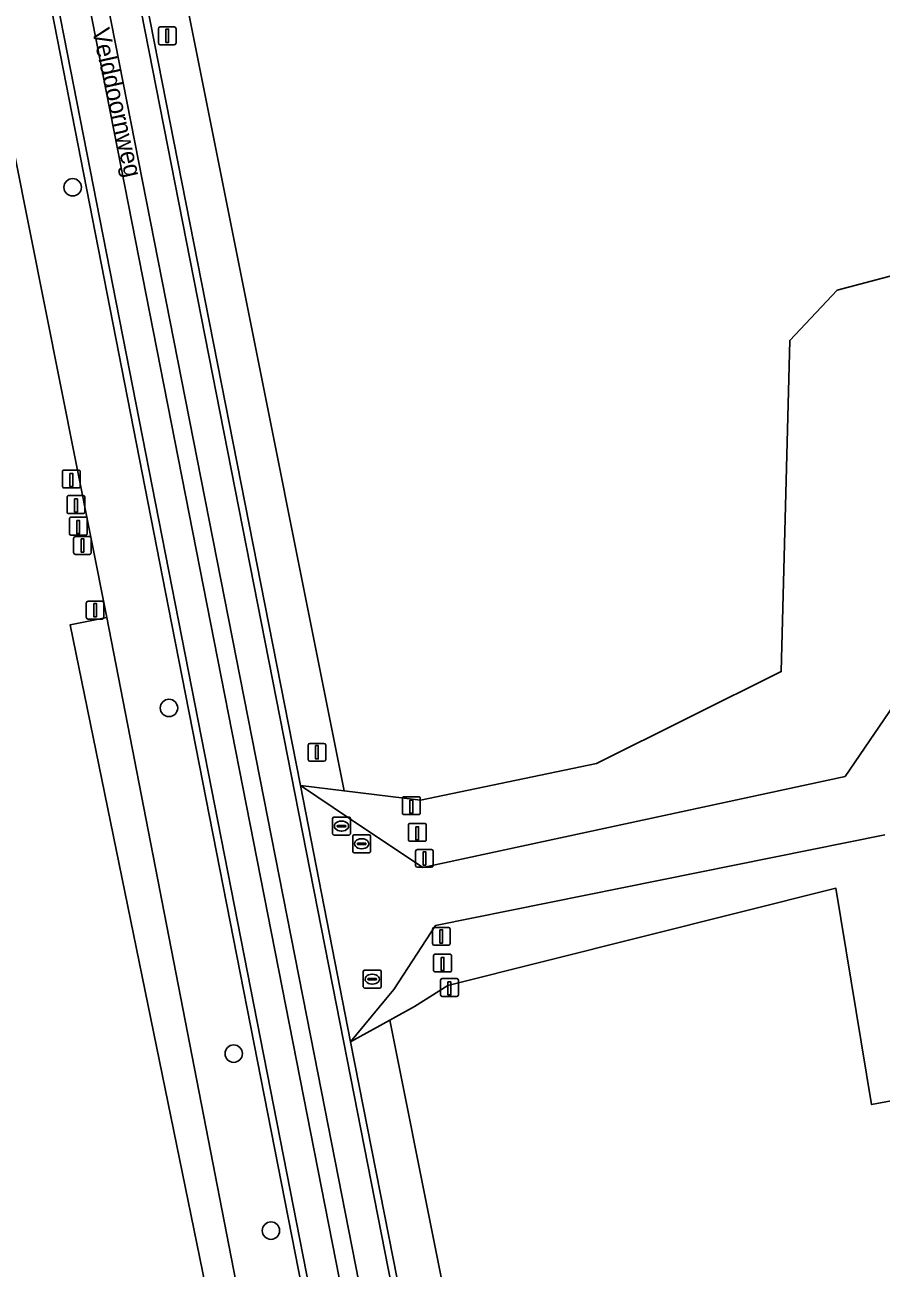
# Model space of a CAD drawing. Extents: x 160203 to 161530, y 379528 to 381797.
# Drawn here: x 160875 to 160923.2, y 380067.5 to 380137.4 of the extents above; entities that cross this region are included whole.
import ezdxf

# ---------------------------------------------------------------- set-up
doc = ezdxf.new("R2010")
doc.units = 0
for name, color, linetype in [('IMGEO_Afsluitpaal', 7, 'Continuous'), ('IMGEO_Berm_groen', 7, 'Continuous'), ('IMGEO_Berm_open', 7, 'Continuous'), ('IMGEO_Boom', 7, 'Continuous'), ('IMGEO_Brandkraan', 7, 'Continuous'), ('IMGEO_Groenvoorziening', 7, 'Continuous'), ('IMGEO_Lichtmast', 7, 'Continuous'), ('IMGEO_Loofbos', 7, 'Continuous'), ('IMGEO_Openbare_ruimte_label', 7, 'Continuous'), ('IMGEO_Paal', 7, 'Continuous'), ('IMGEO_Rijbaan_lokaal_gesloten', 7, 'Continuous'), ('IMGEO_Rijbaan_lokaal_halfverhard', 7, 'Continuous'), ('IMGEO_Rijbaan_lokaal_open', 7, 'Continuous'), ('IMGEO_Waterloop', 7, 'Continuous')]:
    doc.layers.add(name, color=color, linetype=linetype)

msp = doc.modelspace()

# ---------------------------------------------------------------- linework, layer by layer
at = {"layer": 'IMGEO_Afsluitpaal'}
for p, q in [((160877.74, 380107.756), (160877.74, 380108.556)), ((160877.74, 380108.556), (160877.74, 380107.756)), ((160877.84, 380108.656), (160878.63, 380108.656)), ((160878.63, 380108.656), (160877.84, 380108.656)), ((160878.73, 380108.556), (160878.73, 380107.756)), ((160878.73, 380107.756), (160878.73, 380108.556)), ((160878.63, 380107.656), (160877.84, 380107.656)), ((160877.84, 380107.656), (160878.63, 380107.656)), ((160878.449, 380104.117), (160878.449, 380104.917)), ((160878.449, 380104.917), (160878.449, 380104.117)), ((160878.549, 380105.017), (160879.339, 380105.017)), ((160879.339, 380105.017), (160878.549, 380105.017)), ((160879.439, 380104.917), (160879.439, 380104.117)), ((160879.439, 380104.117), (160879.439, 380104.917)), ((160879.339, 380104.017), (160878.549, 380104.017)), ((160878.549, 380104.017), (160879.339, 380104.017)), ((160896.986, 380090.153), (160896.986, 380090.953)), ((160896.986, 380090.953), (160896.986, 380090.153)), ((160897.086, 380091.053), (160897.876, 380091.053)), ((160897.876, 380091.053), (160897.086, 380091.053)), ((160897.976, 380090.953), (160897.976, 380090.153)), ((160897.976, 380090.153), (160897.976, 380090.953)), ((160897.876, 380090.053), (160897.086, 380090.053)), ((160897.086, 380090.053), (160897.876, 380090.053)), ((160897.937, 380085.769), (160897.937, 380086.569)), ((160897.937, 380086.569), (160897.937, 380085.769)), ((160898.037, 380086.669), (160898.827, 380086.669)), ((160898.827, 380086.669), (160898.037, 380086.669)), ((160898.927, 380086.569), (160898.927, 380085.769)), ((160898.927, 380085.769), (160898.927, 380086.569)), ((160898.827, 380085.669), (160898.037, 380085.669)), ((160898.037, 380085.669), (160898.827, 380085.669))]:
    msp.add_line(p, q, dxfattribs=at)
for points in [[(160878.16, 380108.531), (160878.31, 380108.531), (160878.31, 380107.781), (160878.16, 380107.781), (160878.16, 380108.531)], [(160878.869, 380104.892), (160879.019, 380104.892), (160879.019, 380104.142), (160878.869, 380104.142), (160878.869, 380104.892)], [(160897.406, 380090.928), (160897.556, 380090.928), (160897.556, 380090.178), (160897.406, 380090.178), (160897.406, 380090.928)], [(160898.357, 380086.544), (160898.507, 380086.544), (160898.507, 380085.794), (160898.357, 380085.794), (160898.357, 380086.544)]]:
    msp.add_lwpolyline(points, dxfattribs=at)
for centre, start, end in [((160877.84, 380108.556), 90, 180), ((160877.84, 380108.556), 90, 180), ((160878.63, 380108.556), 0, 90), ((160878.63, 380108.556), 360, 90), ((160877.84, 380107.756), 180, 270), ((160877.84, 380107.756), 180, 270), ((160878.63, 380107.756), 270, 0), ((160878.63, 380107.756), 270, 0), ((160878.549, 380104.917), 90, 180), ((160878.549, 380104.917), 90, 180), ((160879.339, 380104.917), 0, 90), ((160879.339, 380104.917), 360, 90), ((160878.549, 380104.117), 180, 270), ((160878.549, 380104.117), 180, 270), ((160879.339, 380104.117), 270, 0), ((160879.339, 380104.117), 270, 0), ((160897.086, 380090.953), 90, 180), ((160897.086, 380090.953), 90, 180), ((160897.876, 380090.953), 0, 90), ((160897.876, 380090.953), 360, 90), ((160897.086, 380090.153), 180, 270), ((160897.086, 380090.153), 180, 270), ((160897.876, 380090.153), 270, 0), ((160897.876, 380090.153), 270, 0), ((160898.037, 380086.569), 90, 180), ((160898.037, 380086.569), 90, 180), ((160898.827, 380086.569), 0, 90), ((160898.827, 380086.569), 360, 90), ((160898.037, 380085.769), 180, 270), ((160898.037, 380085.769), 180, 270), ((160898.827, 380085.769), 270, 0), ((160898.827, 380085.769), 270, 0)]:
    msp.add_arc(centre, 0.1, start, end, dxfattribs=at)
at = {"layer": 'IMGEO_Berm_groen'}
msp.add_lwpolyline([(160895.533, 380081.45), (160893.315, 380080.226), (160905.256, 380019.672), (160908.269, 380017.71)], close=True, dxfattribs=at)
at = {"layer": 'IMGEO_Berm_open'}
msp.add_lwpolyline([(160867.75, 380199.041), (160861.56, 380230.469), (160858.975, 380243.591), (160857.899, 380243.338), (160860.551, 380229.96), (160866.722, 380198.834), (160874.382, 380160.192), (160915.855, 379949.015), (160917.449, 379940.569), (160918.479, 379940.789), (160916.864, 379949.182), (160891.303, 380079.455)], close=True, dxfattribs=at)
at = {"layer": 'IMGEO_Boom'}
for centre in [(160877.685, 380128.302), (160883.106, 380099.015), (160886.747, 380079.57), (160888.845, 380069.614)]:
    msp.add_circle(centre, 0.489, dxfattribs=at)
at = {"layer": 'IMGEO_Brandkraan'}
for p, q in [((160892.388, 380092.869), (160893.24, 380092.869)), ((160892.313, 380091.943), (160892.313, 380092.795)), ((160892.572, 380092.363), (160892.572, 380092.375)), ((160893.01, 380092.326), (160892.612, 380092.326)), ((160892.615, 380092.412), (160893.013, 380092.412)), ((160892.801, 380092.649), (160892.826, 380092.649)), ((160893.056, 380092.375), (160893.056, 380092.363)), ((160893.314, 380092.795), (160893.314, 380091.943)), ((160893.24, 380091.869), (160892.388, 380091.869)), ((160892.824, 380092.089), (160892.799, 380092.089)), ((160893.448, 380090.949), (160893.448, 380091.801)), ((160893.523, 380091.875), (160894.375, 380091.875)), ((160893.75, 380091.418), (160894.148, 380091.418)), ((160893.936, 380091.655), (160893.961, 380091.655)), ((160894.449, 380091.801), (160894.449, 380090.949)), ((160894.375, 380090.875), (160893.523, 380090.875)), ((160893.707, 380091.369), (160893.707, 380091.381)), ((160894.145, 380091.332), (160893.747, 380091.332)), ((160893.959, 380091.095), (160893.934, 380091.095)), ((160894.191, 380091.381), (160894.191, 380091.369)), ((160894.042, 380083.334), (160894.042, 380084.186)), ((160894.117, 380084.26), (160894.969, 380084.26)), ((160894.301, 380083.754), (160894.301, 380083.766)), ((160894.739, 380083.717), (160894.341, 380083.717)), ((160894.344, 380083.803), (160894.742, 380083.803)), ((160894.53, 380084.04), (160894.555, 380084.04)), ((160894.785, 380083.766), (160894.785, 380083.754)), ((160895.043, 380084.186), (160895.043, 380083.334)), ((160894.969, 380083.26), (160894.117, 380083.26)), ((160894.553, 380083.48), (160894.528, 380083.48))]:
    msp.add_line(p, q, dxfattribs=at)
for points in [[(160892.388, 380092.869), (160893.24, 380092.869)], [(160892.313, 380091.943), (160892.313, 380092.795)], [(160893.314, 380092.795), (160893.314, 380091.943)], [(160893.24, 380091.869), (160892.388, 380091.869)], [(160893.448, 380090.949), (160893.448, 380091.801)], [(160893.523, 380091.875), (160894.375, 380091.875)], [(160894.449, 380091.801), (160894.449, 380090.949)], [(160894.375, 380090.875), (160893.523, 380090.875)], [(160894.042, 380083.334), (160894.042, 380084.186)], [(160894.117, 380084.26), (160894.969, 380084.26)], [(160895.043, 380084.186), (160895.043, 380083.334)], [(160894.969, 380083.26), (160894.117, 380083.26)]]:
    msp.add_lwpolyline(points, dxfattribs=at)
for centre, radius, start, end in [((160892.39, 380092.793), 0.0765, 91.55205, 178.44795), ((160892.39, 380092.793), 0.0765, 91.55205, 178.44795), ((160893.238, 380092.793), 0.0765, 1.55205, 88.44795), ((160893.238, 380092.793), 0.0765, 1.55205, 88.44795), ((160892.612, 380092.372), 0.0403, 85.87752, 175.75265), ((160892.609, 380092.362), 0.0366, 178.93798, 274.71019), ((160893.013, 380092.369), 0.043, 264.86636, 352.45326), ((160893.017, 380092.374), 0.0386, 1.73085, 96.63898), ((160892.39, 380091.945), 0.0765, 181.55205, 268.44795), ((160892.39, 380091.945), 0.0765, 181.55205, 268.44795), ((160893.238, 380091.945), 0.0765, 271.55205, 358.44795), ((160893.238, 380091.945), 0.0765, 271.55205, 358.44795), ((160893.525, 380091.799), 0.0765, 91.55205, 178.44795), ((160893.525, 380091.799), 0.0765, 91.55205, 178.44795), ((160893.747, 380091.378), 0.0403, 85.87752, 175.75265), ((160894.152, 380091.38), 0.0386, 1.73085, 96.63898), ((160894.373, 380091.799), 0.0765, 1.55205, 88.44795), ((160894.373, 380091.799), 0.0765, 1.55205, 88.44795), ((160893.525, 380090.951), 0.0765, 181.55205, 268.44795), ((160893.525, 380090.951), 0.0765, 181.55205, 268.44795), ((160893.744, 380091.368), 0.0366, 178.93798, 274.71019), ((160894.148, 380091.375), 0.043, 264.86636, 352.45326), ((160894.373, 380090.951), 0.0765, 271.55205, 358.44795), ((160894.373, 380090.951), 0.0765, 271.55205, 358.44795), ((160894.119, 380084.184), 0.0765, 91.55205, 178.44795), ((160894.119, 380084.184), 0.0765, 91.55205, 178.44795), ((160894.341, 380083.763), 0.0403, 85.87752, 175.75265), ((160894.338, 380083.753), 0.0366, 178.93798, 274.71019), ((160894.742, 380083.76), 0.043, 264.86636, 352.45326), ((160894.746, 380083.765), 0.0386, 1.73085, 96.63898), ((160894.967, 380084.184), 0.0765, 1.55205, 88.44795), ((160894.967, 380084.184), 0.0765, 1.55205, 88.44795), ((160894.119, 380083.336), 0.0765, 181.55205, 268.44795), ((160894.119, 380083.336), 0.0765, 181.55205, 268.44795), ((160894.967, 380083.336), 0.0765, 271.55205, 358.44795), ((160894.967, 380083.336), 0.0765, 271.55205, 358.44795)]:
    msp.add_arc(centre, radius, start, end, dxfattribs=at)
for centre, major_axis, ratio, start_param, end_param in [((160892.8, 380092.369), (-0.387, 0.002), 0.722429, 4.712389, 7.853982), ((160892.825, 380092.369), (-0.39, 0.002), 0.717154, 1.570796, 4.712389), ((160893.935, 380091.375), (-0.387, 0.002), 0.722429, 4.712389, 7.853982), ((160893.96, 380091.375), (-0.39, 0.002), 0.717154, 1.570796, 4.712389), ((160894.529, 380083.76), (-0.387, 0.002), 0.722429, 4.712389, 7.853982), ((160894.554, 380083.76), (-0.39, 0.002), 0.717154, 1.570796, 4.712389)]:
    msp.add_ellipse(centre, major_axis=major_axis, ratio=ratio, start_param=start_param, end_param=end_param, dxfattribs=at)
at = {"layer": 'IMGEO_Groenvoorziening'}
for points in [[(160858.585, 380228.968), (160856.352, 380240.258), (160852.661, 380239.334), (160879.617, 380104.11), (160888.682, 380057.421), (160900.057, 380000), (160907.97, 379960.368), (160913.18, 379936.681), (160911.655, 379936.379), (160912.186, 379932.168), (160913.952, 379932.527), (160916.604, 379919.613), (160923.442, 379886.324)], [(160926.044, 379887.123), (160925.694, 379888.565), (160919.399, 379920.083), (160913.703, 379948.599), (160883.085, 380104.658), (160872.358, 380159.336), (160864.629, 380198.41), (160858.585, 380228.968)], [(160939.157, 380115.876), (160930.535, 380117.947), (160928.697, 380120.046), (160927.725, 380124.364), (160920.712, 380122.517), (160918.035, 380119.689), (160917.557, 380101.063), (160907.156, 380095.894), (160897.258, 380093.833), (160892.955, 380094.353), (160890.502, 380094.649), (160893.265, 380092.8), (160897.383, 380090.043), (160921.152, 380095.162), (160925.838, 380101.995)], [(160923.39, 380091.872), (160898.101, 380086.776), (160895.76, 380083.184), (160895.298, 380082.625), (160893.315, 380080.226), (160895.533, 380081.45), (160896.929, 380082.22), (160898.801, 380083.398), (160920.634, 380088.87), (160922.642, 380076.701), (160947.339, 380081.313)]]:
    msp.add_lwpolyline(points, dxfattribs=at)
msp.add_lwpolyline([(160892.955, 380094.353), (160879.549, 380161.442), (160877.378, 380161.397), (160890.502, 380094.649)], close=True, dxfattribs=at)
at = {"layer": 'IMGEO_Lichtmast'}
for p, q in [((160882.514, 380136.424), (160882.514, 380137.224)), ((160882.514, 380137.224), (160882.514, 380136.424)), ((160882.614, 380137.324), (160883.404, 380137.324)), ((160883.404, 380137.324), (160882.614, 380137.324)), ((160883.504, 380137.224), (160883.504, 380136.424)), ((160883.504, 380136.424), (160883.504, 380137.224)), ((160883.404, 380136.324), (160882.614, 380136.324)), ((160882.614, 380136.324), (160883.404, 380136.324)), ((160891.039, 380097.02), (160891.829, 380097.02)), ((160891.829, 380097.02), (160891.039, 380097.02)), ((160890.939, 380096.12), (160890.939, 380096.92)), ((160890.939, 380096.92), (160890.939, 380096.12)), ((160891.929, 380096.92), (160891.929, 380096.12)), ((160891.929, 380096.12), (160891.929, 380096.92)), ((160891.829, 380096.02), (160891.039, 380096.02)), ((160891.039, 380096.02), (160891.829, 380096.02))]:
    msp.add_line(p, q, dxfattribs=at)
for points in [[(160882.934, 380137.199), (160883.084, 380137.199), (160883.084, 380136.449), (160882.934, 380136.449), (160882.934, 380137.199)], [(160891.359, 380096.895), (160891.509, 380096.895), (160891.509, 380096.145), (160891.359, 380096.145), (160891.359, 380096.895)]]:
    msp.add_lwpolyline(points, dxfattribs=at)
for centre, start, end in [((160882.614, 380137.224), 90, 180), ((160882.614, 380137.224), 90, 180), ((160883.404, 380137.224), 0, 90), ((160883.404, 380137.224), 360, 90), ((160882.614, 380136.424), 180, 270), ((160882.614, 380136.424), 180, 270), ((160883.404, 380136.424), 270, 0), ((160883.404, 380136.424), 270, 0), ((160891.039, 380096.92), 90, 180), ((160891.039, 380096.92), 90, 180), ((160891.829, 380096.92), 0, 90), ((160891.829, 380096.92), 360, 90), ((160891.039, 380096.12), 180, 270), ((160891.039, 380096.12), 180, 270), ((160891.829, 380096.12), 270, 0), ((160891.829, 380096.12), 270, 0)]:
    msp.add_arc(centre, 0.1, start, end, dxfattribs=at)
at = {"layer": 'IMGEO_Loofbos'}
for points in [[(160885.486, 380064.948), (160877.546, 380103.697), (160879.617, 380104.11), (160852.661, 380239.334)], [(160879.549, 380161.442), (160892.955, 380094.353), (160897.258, 380093.833), (160907.156, 380095.894), (160917.557, 380101.063), (160918.035, 380119.689), (160920.712, 380122.517), (160927.725, 380124.364), (160928.697, 380120.046), (160930.535, 380117.947), (160939.157, 380115.876), (160947.339, 380081.313), (160922.642, 380076.701), (160920.634, 380088.87), (160898.801, 380083.398), (160896.929, 380082.22), (160895.533, 380081.45), (160908.269, 380017.71)]]:
    msp.add_lwpolyline(points, dxfattribs=at)
at = {"layer": 'IMGEO_Paal'}
for p, q in [((160878.031, 380112.396), (160877.19, 380112.396)), ((160878.031, 380112.396), (160877.19, 380112.396)), ((160877.115, 380112.312), (160877.115, 380111.471)), ((160877.115, 380112.312), (160877.115, 380111.471)), ((160878.115, 380111.48), (160878.115, 380112.321)), ((160878.115, 380111.48), (160878.115, 380112.321)), ((160877.199, 380111.396), (160878.04, 380111.396)), ((160877.199, 380111.396), (160878.04, 380111.396)), ((160877.375, 380110.873), (160877.375, 380110.032)), ((160877.375, 380110.873), (160877.375, 380110.032)), ((160878.291, 380110.957), (160877.45, 380110.957)), ((160878.291, 380110.957), (160877.45, 380110.957)), ((160878.375, 380110.041), (160878.375, 380110.882)), ((160878.375, 380110.041), (160878.375, 380110.882)), ((160877.459, 380109.957), (160878.3, 380109.957)), ((160877.459, 380109.957), (160878.3, 380109.957)), ((160877.5, 380109.659), (160877.5, 380108.818)), ((160877.5, 380109.659), (160877.5, 380108.818)), ((160878.416, 380109.743), (160877.575, 380109.743)), ((160878.416, 380109.743), (160877.575, 380109.743)), ((160878.5, 380108.827), (160878.5, 380109.668)), ((160878.5, 380108.827), (160878.5, 380109.668)), ((160877.584, 380108.743), (160878.425, 380108.743)), ((160877.584, 380108.743), (160878.425, 380108.743)), ((160896.246, 380093.932), (160896.246, 380093.091)), ((160896.246, 380093.932), (160896.246, 380093.091)), ((160897.162, 380094.016), (160896.321, 380094.016)), ((160897.162, 380094.016), (160896.321, 380094.016)), ((160897.246, 380093.1), (160897.246, 380093.941)), ((160897.246, 380093.1), (160897.246, 380093.941)), ((160896.33, 380093.016), (160897.171, 380093.016)), ((160896.33, 380093.016), (160897.171, 380093.016)), ((160896.581, 380092.434), (160896.581, 380091.593)), ((160896.581, 380092.434), (160896.581, 380091.593)), ((160897.497, 380092.518), (160896.656, 380092.518)), ((160897.497, 380092.518), (160896.656, 380092.518)), ((160897.581, 380091.602), (160897.581, 380092.443)), ((160897.581, 380091.602), (160897.581, 380092.443)), ((160896.665, 380091.518), (160897.506, 380091.518)), ((160896.665, 380091.518), (160897.506, 380091.518)), ((160898.916, 380085.168), (160898.075, 380085.168)), ((160898.916, 380085.168), (160898.075, 380085.168)), ((160898, 380085.084), (160898, 380084.243)), ((160898, 380085.084), (160898, 380084.243)), ((160899, 380084.252), (160899, 380085.093)), ((160899, 380084.252), (160899, 380085.093)), ((160898.084, 380084.168), (160898.925, 380084.168)), ((160898.084, 380084.168), (160898.925, 380084.168)), ((160898.392, 380083.708), (160898.392, 380082.867)), ((160898.392, 380083.708), (160898.392, 380082.867)), ((160899.308, 380083.792), (160898.467, 380083.792)), ((160899.308, 380083.792), (160898.467, 380083.792)), ((160899.392, 380082.876), (160899.392, 380083.717)), ((160899.392, 380082.876), (160899.392, 380083.717)), ((160898.476, 380082.792), (160899.317, 380082.792)), ((160898.476, 380082.792), (160899.317, 380082.792))]:
    msp.add_line(p, q, dxfattribs=at)
for points in [[(160877.53, 380112.209), (160877.69, 380112.209), (160877.69, 380111.476), (160877.53, 380111.476), (160877.53, 380112.209)], [(160877.79, 380110.77), (160877.95, 380110.77), (160877.95, 380110.037), (160877.79, 380110.037), (160877.79, 380110.77)], [(160877.915, 380109.556), (160878.075, 380109.556), (160878.075, 380108.823), (160877.915, 380108.823), (160877.915, 380109.556)], [(160896.661, 380093.829), (160896.821, 380093.829), (160896.821, 380093.096), (160896.661, 380093.096), (160896.661, 380093.829)], [(160896.996, 380092.331), (160897.156, 380092.331), (160897.156, 380091.598), (160896.996, 380091.598), (160896.996, 380092.331)], [(160898.415, 380084.981), (160898.575, 380084.981), (160898.575, 380084.248), (160898.415, 380084.248), (160898.415, 380084.981)], [(160898.807, 380083.605), (160898.967, 380083.605), (160898.967, 380082.872), (160898.807, 380082.872), (160898.807, 380083.605)]]:
    msp.add_lwpolyline(points, dxfattribs=at)
for centre, start, end in [((160877.193, 380112.318), 92.4484, 184.28452), ((160877.193, 380112.318), 92.4484, 184.28452), ((160878.037, 380112.318), 2.4484, 94.28452), ((160878.037, 380112.318), 2.4484, 94.28452), ((160877.193, 380111.474), 182.4484, 274.28452), ((160877.193, 380111.474), 182.4484, 274.28452), ((160878.037, 380111.474), 272.4484, 4.28452), ((160878.037, 380111.474), 272.4484, 4.28452), ((160877.453, 380110.879), 92.4484, 184.28452), ((160877.453, 380110.879), 92.4484, 184.28452), ((160878.297, 380110.879), 2.4484, 94.28452), ((160878.297, 380110.879), 2.4484, 94.28452), ((160877.453, 380110.035), 182.4484, 274.28452), ((160877.453, 380110.035), 182.4484, 274.28452), ((160877.578, 380109.665), 92.4484, 184.28452), ((160877.578, 380109.665), 92.4484, 184.28452), ((160878.297, 380110.035), 272.4484, 4.28452), ((160878.297, 380110.035), 272.4484, 4.28452), ((160878.422, 380109.665), 2.4484, 94.28452), ((160878.422, 380109.665), 2.4484, 94.28452), ((160877.578, 380108.821), 182.4484, 274.28452), ((160877.578, 380108.821), 182.4484, 274.28452), ((160878.422, 380108.821), 272.4484, 4.28452), ((160878.422, 380108.821), 272.4484, 4.28452), ((160896.324, 380093.938), 92.4484, 184.28452), ((160896.324, 380093.938), 92.4484, 184.28452), ((160897.168, 380093.938), 2.4484, 94.28452), ((160897.168, 380093.938), 2.4484, 94.28452), ((160896.324, 380093.094), 182.4484, 274.28452), ((160896.324, 380093.094), 182.4484, 274.28452), ((160897.168, 380093.094), 272.4484, 4.28452), ((160897.168, 380093.094), 272.4484, 4.28452), ((160896.659, 380092.44), 92.4484, 184.28452), ((160896.659, 380092.44), 92.4484, 184.28452), ((160897.503, 380092.44), 2.4484, 94.28452), ((160897.503, 380092.44), 2.4484, 94.28452), ((160896.659, 380091.596), 182.4484, 274.28452), ((160896.659, 380091.596), 182.4484, 274.28452), ((160897.503, 380091.596), 272.4484, 4.28452), ((160897.503, 380091.596), 272.4484, 4.28452), ((160898.078, 380085.09), 92.4484, 184.28452), ((160898.078, 380085.09), 92.4484, 184.28452), ((160898.922, 380085.09), 2.4484, 94.28452), ((160898.922, 380085.09), 2.4484, 94.28452), ((160898.078, 380084.246), 182.4484, 274.28452), ((160898.078, 380084.246), 182.4484, 274.28452), ((160898.47, 380083.714), 92.4484, 184.28452), ((160898.47, 380083.714), 92.4484, 184.28452), ((160898.922, 380084.246), 272.4484, 4.28452), ((160898.922, 380084.246), 272.4484, 4.28452), ((160899.314, 380083.714), 2.4484, 94.28452), ((160899.314, 380083.714), 2.4484, 94.28452), ((160898.47, 380082.87), 182.4484, 274.28452), ((160898.47, 380082.87), 182.4484, 274.28452), ((160899.314, 380082.87), 272.4484, 4.28452), ((160899.314, 380082.87), 272.4484, 4.28452)]:
    msp.add_arc(centre, 0.0779, start, end, dxfattribs=at)
at = {"layer": 'IMGEO_Rijbaan_lokaal_gesloten'}
for points in [[(160869.506, 380199.393), (160867.75, 380199.041), (160891.303, 380079.455), (160916.864, 379949.182), (160918.479, 379940.789), (160917.449, 379940.569), (160919.243, 379931.834), (160920.254, 379932.032), (160921.392, 379926.322), (160923.141, 379926.741), (160919.01, 379947.114), (160918.701, 379948.964), (160892.944, 380080.195)], [(160866.722, 380198.834), (160865.008, 380198.49), (160872.738, 380159.431), (160914.093, 379948.69), (160918.669, 379925.757), (160920.383, 379926.099), (160919.243, 379931.834), (160917.449, 379940.569), (160915.855, 379949.015), (160874.382, 380160.192)]]:
    msp.add_lwpolyline(points, close=True, dxfattribs=at)
at = {"layer": 'IMGEO_Rijbaan_lokaal_halfverhard'}
msp.add_lwpolyline([(160925.838, 380101.995), (160921.152, 380095.162), (160897.383, 380090.043), (160893.265, 380092.8), (160890.502, 380094.649), (160893.315, 380080.226), (160895.298, 380082.625), (160895.76, 380083.184), (160898.101, 380086.776), (160923.39, 380091.872)], dxfattribs=at)
at = {"layer": 'IMGEO_Rijbaan_lokaal_open'}
for points in [[(160869.919, 380199.476), (160869.506, 380199.393), (160892.944, 380080.195), (160918.701, 379948.964), (160919.01, 379947.114), (160919.082, 379949.05), (160918.097, 379954.072), (160918.093, 379954.094), (160917.183, 379958.747), (160908.104, 380005.176), (160905.256, 380019.672), (160893.315, 380080.226), (160890.502, 380094.649), (160877.378, 380161.397), (160874.447, 380176.442)], [(160865.008, 380198.49), (160864.629, 380198.41), (160872.358, 380159.336), (160883.085, 380104.658), (160913.703, 379948.599), (160919.399, 379920.083), (160925.694, 379888.565), (160926.044, 379887.123), (160926.309, 379887.469), (160919.788, 379920.148), (160918.669, 379925.757), (160914.093, 379948.69), (160872.738, 380159.431)]]:
    msp.add_lwpolyline(points, close=True, dxfattribs=at)
at = {"layer": 'IMGEO_Waterloop'}
msp.add_lwpolyline([(160911.655, 379936.379), (160913.18, 379936.681), (160907.97, 379960.368), (160900.057, 380000), (160888.682, 380057.421), (160879.617, 380104.11), (160877.546, 380103.697), (160885.486, 380064.948), (160898.502, 380000), (160905.312, 379965.886)], close=True, dxfattribs=at)

# ---------------------------------------------------------------- texts
at = {"layer": 'IMGEO_Openbare_ruimte_label'}
msp.add_text('Velddoornweg', height=1, rotation=282.59095, dxfattribs=at).set_placement((160878.771, 380137.139))

doc.saveas('drawing.dxf')
